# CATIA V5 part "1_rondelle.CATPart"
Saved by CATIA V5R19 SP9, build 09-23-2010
Part number: 1_rondelle
Revision: ANY
Definition: UNKNOWN
Nomenclature: 1_rondelle
Source: Unknown
Bounding box of the stored display mesh (mm): x -65 to 64.818, y 0 to 15, z -65 to 65
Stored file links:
  Y:\fin de projet cabestan poupee\1_rondelle.CATPart
  Ass_arbre poupee_1.CATProduct
  Y:\bricolage cabestan\6_axe.CATPart
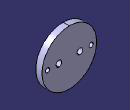
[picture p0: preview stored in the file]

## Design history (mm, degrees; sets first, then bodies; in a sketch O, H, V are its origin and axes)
Set1
  Sketch1 on face of Solid1, origin (0, 15, 0), H (-1, 0, 0), V (0, 0, 1)
    circle A1 centre (52, 0) radius 5.25
    reference projected arc E1 centre (52, 0) radius 6 from (52, -6) to (52, 6) ccw from edge of DatumCurve1
    radius A1 = 5.25
    concentricity: A1 E1
  DatumCurve1
  DatumPoint1
Body1 "NONE" (main body)
  Solid1: solid without history
  DatumSurface1
  Pocket1: profile Sketch1, direction (0, -1, 0), up to face of DatumSurface1
  CircPattern1: of Pocket1, instances 2, angular step 180, axis from face of Solid1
